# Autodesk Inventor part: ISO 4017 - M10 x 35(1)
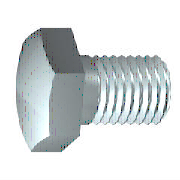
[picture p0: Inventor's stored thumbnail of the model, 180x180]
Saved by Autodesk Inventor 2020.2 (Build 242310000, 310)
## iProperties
Created: 2019-01
Part Number: ISO 4017 - M10 x 35(1)
Material: Stahl, weich
Description: Sechskantschraube
Document SubType Name: Modeling
Standard: DIN EN 24 017
Designer: lutzd
Standards Organization: DIN
Language: de-DE
Size Designation: M10 x 35
Categories: <MemberInstance><Categories><Category DisplayName="Verbindungselemente" InternalName="e4da775c-781d-43d5-af7c-5136215cf5a6" Mnemonic="FSTN"><Category DisplayNam
Mass: 32.3319 g
Surface Area: 18.6358 cm^2
Volume: 4.11872 cm^3
Density: 7.85 g/cm^3
Appearance: Halbpoliert
IsCustomPart: 0
Author: lutzd
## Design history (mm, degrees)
workplane "Work Plane1"
sketch "Skizze1"
  geometry: L1 (0, 7.315)-(0, 5); L2 (4.5, 5)-(35, 5); L3 (35, 5)-(35, 0); L4 (35, 0)-(-0.6, 0); L5 (-7.72, 0)-(42.12, 0) reference; L6 (-0.6, 0)-(-0.6, 7.315); L7 (-0.6, 7.315)-(0, 7.315); L8 (4.5, 5)-(3.58, 5); L9 (3.58, 5)-(0, 5); L10 (0, -1.463)-(0, 8.778) reference
  constraints: 16 end point, 2 collinear, 2 perpendicular, 1 parallel
  dimensions: "d0" = 35 distance between parallel lines of L3 L1 (= NLG); "d1" = 30.5 distance from line of L2.start L3 (= GEL); "d2" = 10 diameter of L2 L4 (= GD); "d9" = 0.6001 distance between parallel lines of L6 L1 (computed from SD); "d10" = 14.63 diameter of L7 L4 (= SD2); "d13" = 0.92028 distance of L2.start L8.end (computed from GAL); "d14" = 10 diameter of L9 L4 (= BDM)
revolve "Körper" sketch "Skizze1" stored, may be unused: angle "d12" = 90 deg
sketch "Skizze2"
  geometry: L1 (0, 9.238)-(8, 4.619); L2 (8, 4.619)-(8, -4.619); L3 (8, -4.619)-(0, -9.238); L4 (0, -9.238)-(-8, -4.619); L5 (-8, -4.619)-(-8, 4.619); L6 (-8, 4.619)-(0, 9.238); 2 further points
  constraints: 12 end point, 1 coincident, 1 vertical, 11 other
  dimensions: "d11" = 16 distance between parallel lines of L5 L2 (= SW)
extrude "Kopf" join sketch "Skizze2" distance "d3" = 5.8 (= KOH - SD); taper "d4" = 0 deg
sketch "Skizze4"
  geometry: L1 (-6.4, 8)-(-6.4, 9.238); L2 (-6.4, 9.238)-(-5.686, 9.238); L3 (-5.686, 9.238)-(-6.4, 8); L4 (-7.56, 0)-(0.56, 0) reference; L5 (-0.6, 9.238)-(-6.4, 9.238) reference; L6 (-6.4, 4.619)-(-6.4, 9.238) reference
  constraints: 6 end point, 2 collinear, 1 perpendicular, 1 vertical
  dimensions: "d5" = 30 deg angle of L3 L1 (= ANG1); "d19" = 16 diameter of L1.start L4 (= SW0)
revolve "Fase1" stored, may be unused: angle "d21" = 90 deg
body "Solid1"
feature "Gewinde" dims "d15" = 30.5 (= GEL), "d16" = 0
chamfer "Fase2" distance "d6" = 0.92018 (= -0.5 x SPD + 0.5 x GD); stored, may be unused: second distance "d7" = 0.92028 (computed from GUL), angle "d55" = 45 deg
other parameters: "NLG" = 35 [user parameter; used in 1 equation term], "GD" = 10 (= NND) [user parameter; used in 2 equation terms], "BDM" = 10 (= NND) [user parameter; used in 1 equation term], "KOH" = 6.4 [user parameter; used in 1 equation term], "GEL" = 30.5 [user parameter; used in 2 equation terms], "SW" = 16 [user parameter; used in 2 equation terms], "SW0" = 16 (= SW) [user parameter; used in 1 equation term], "SPD" = 8.15965 (= NND - 1.2269 x PTC) [user parameter; used in 1 equation term], "SD2" = 14.63 [user parameter; used in 2 equation terms], "SD" = 0.6 [user parameter; used in 2 equation terms], "ANG1" = 30 deg [user parameter; used in 1 equation term], "GAL" = 0.92018 (= 0.61345 x PTC) [user parameter; used in 1 equation term], "GUL" = 0.92018 (= 0.61345 x PTC) [user parameter; used in 1 equation term], "d8" = 0, "RR" = 0.4 [user parameter], "d57" = 0, "d58" = 0, "TPU" = 6.66667 (computed from PTC) [user parameter], "GD1" = 8.15965 (= THREADDIA - 1.2269 x PTC) [user parameter], "SDH" = 14.63 (= SD2) [user parameter], "SDHG" = 4.5 [user parameter], "TOA" = 30 deg [user parameter], "PTC" = 1.5 [user parameter; used in 5 equation terms], "E0" = 18.48 [user parameter]
